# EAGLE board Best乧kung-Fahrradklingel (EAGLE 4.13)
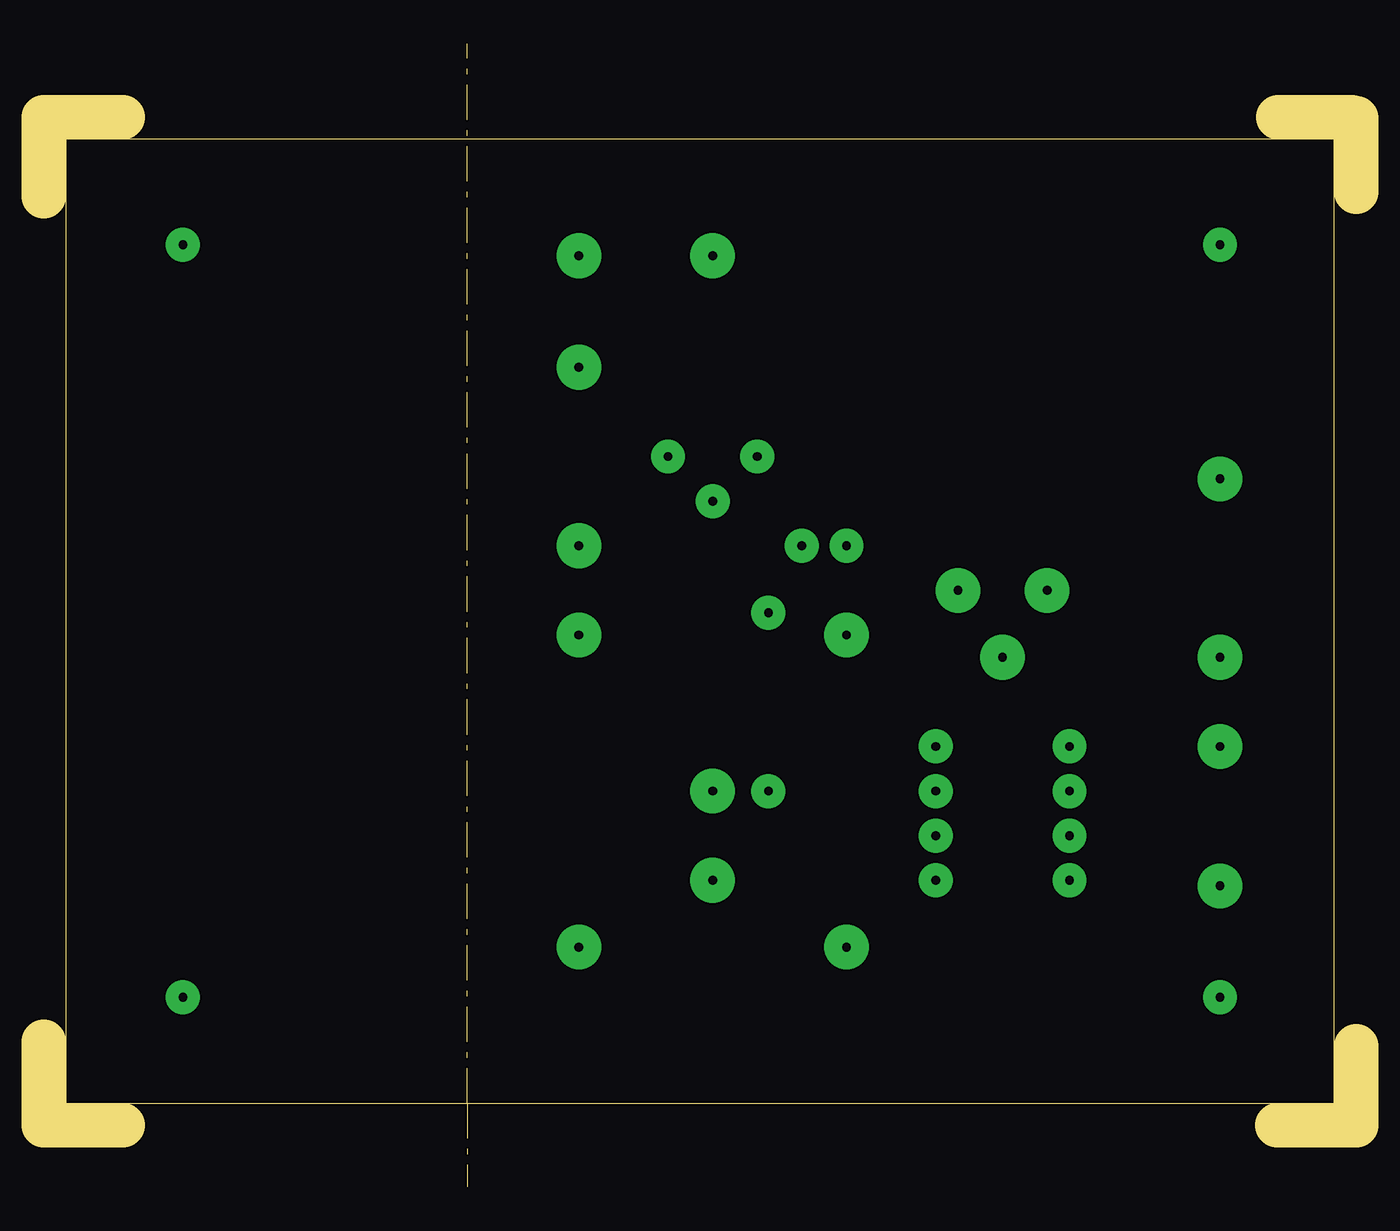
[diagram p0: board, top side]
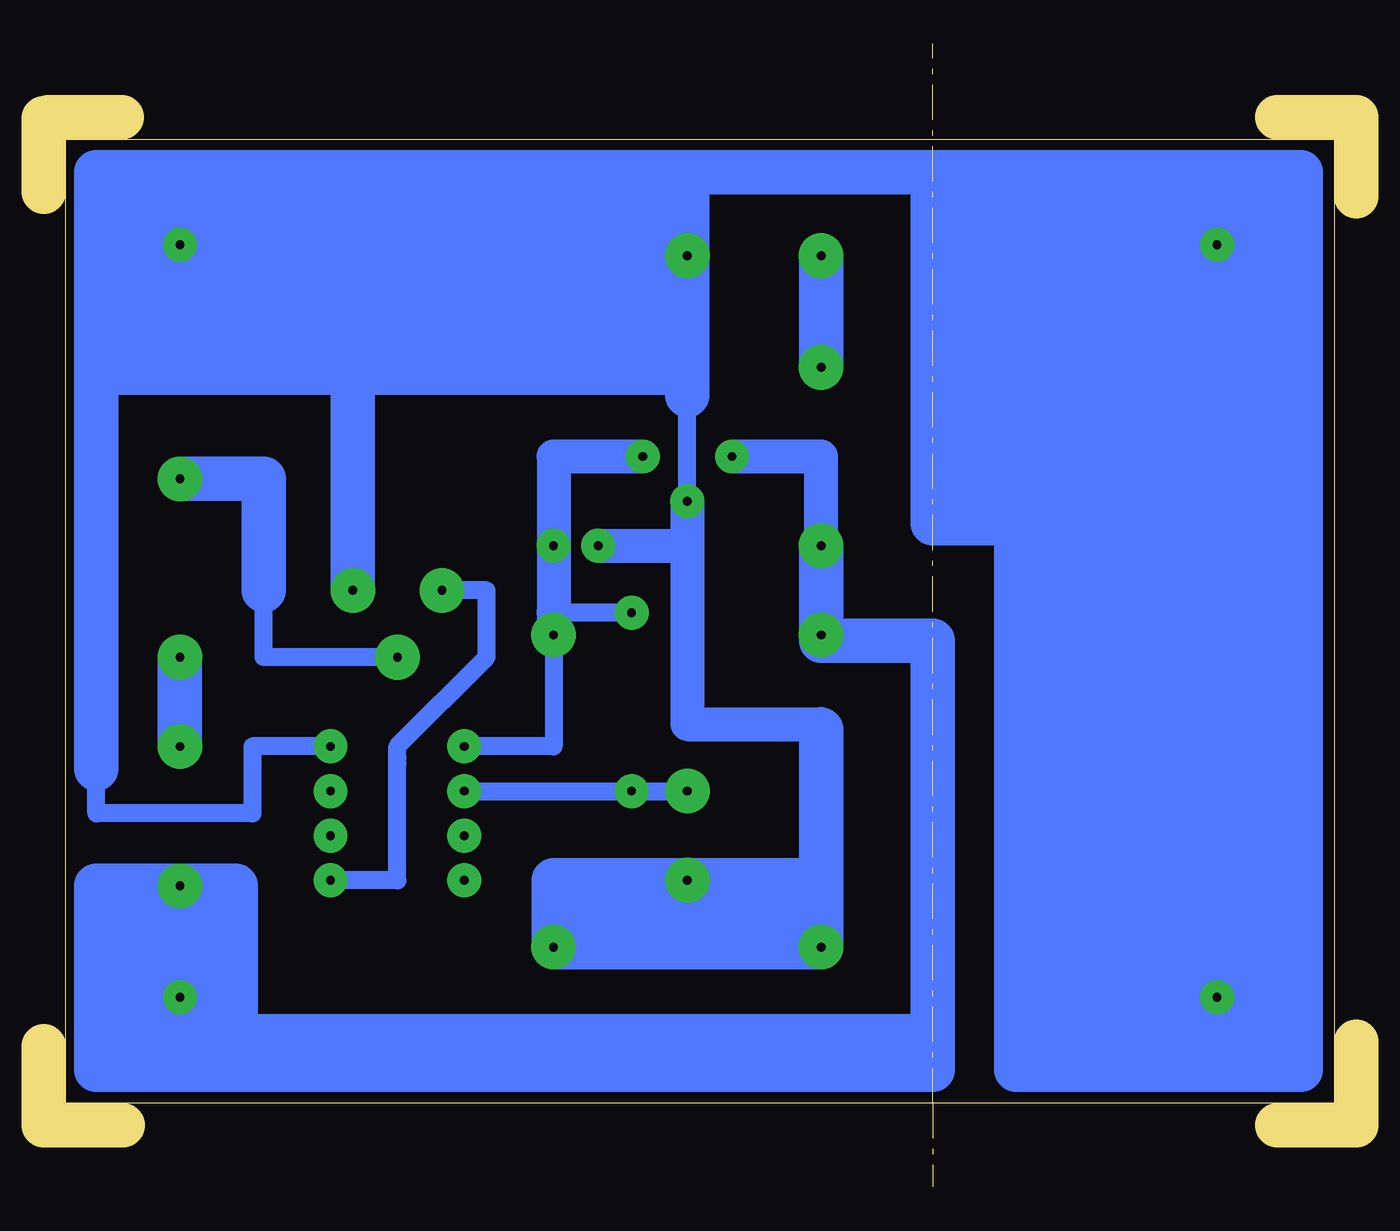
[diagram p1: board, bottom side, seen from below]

Size 74.72 x 65.09 mm. Coordinates in mm from the lower left corner, seen from the top.
Outline: 24.11,4.76 1.25,4.76 1.25,59.67 73.47,59.67 73.47,4.76 24.11,4.76
Outline: 0,56.42 0,60.92 4.5,60.92
Outline: 0,3.76 0,8.26
Outline: 4.5,3.51 0,3.51
Outline: 74.72,60.85 74.72,56.67
Outline: 74.72,8.01 74.72,3.51 70.22,3.51
Outline: 70.29,60.92 74.47,60.92
Outline: 24.11,4.76 24.11,65.09
Outline: 24.11,4.76 24.11,0
Copper layers (1*16): Top 0.035mm / dielectric 1.5mm / Bottom 0.035mm
Design rules "default": minimum track width 10mil, minimum drill 24mil, track to track 8mil, track to pad 8mil, pad to pad 8mil, via to via 8mil, smd to smd 8mil, copper to edge 40mil, drill to drill 8mil, minimum pad ring 10mil, minimum via ring 8mil, stop-mask expansion 4mil, vias tented up to drill 0mil, thermal gap 10mil

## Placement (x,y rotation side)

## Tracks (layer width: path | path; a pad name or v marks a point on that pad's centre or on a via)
S$1  (via drill 0.5 pad 1.93)
  other vias: 7.92,10.79
S$2  (via drill 0.5 pad 1.93)
  other vias: 7.92,53.66
S$3  (via drill 0.5 pad 1.93)
  other vias: 66.97,53.66
S$4  (via drill 0.5 pad 1.93)
  other vias: 66.97,10.79
S$5  (via drill 0.5 pad 2.54)
  Bottom 0.406: v30.46,53.02 v30.46,46.67
  Bottom 2.54: v30.46,53.02 v30.46,46.67
S$6  (via drill 0.5 pad 2.54)
  Bottom 0.406: v66.97,30.16 v66.97,25.08
  Bottom 2.54: v66.97,30.16 v66.97,25.08
S$7
  Bottom 2.54: 71.73,46.04 71.73,23.81
S$8  (via drill 0.5 pad 1.93, 0.5 pad 2.54)
  Bottom 0.406: v30.46,36.51 v30.46,31.43 24.11,31.43 24.11,8.57
  Bottom 1.93: v35.54,41.59 30.46,41.59 v30.46,36.51
  Bottom 2.54: v30.46,31.43 v30.46,36.51 | 30.46,31.11 24.11,31.11 24.11,8.57 | 71.73,14.6 71.73,6.67 24.11,6.67 24.11,8.57 | 71.73,14.6 71.73,16.19 | 24.11,8.57 64.12,8.57 | 71.73,14.6 71.73,17.15 v66.97,17.15 63.8,17.15 63.8,7.3
S$9  (via drill 0.5 pad 1.93, 0.5 pad 2.54)
  Bottom 0.406: 45.7,22.54 46.65,22.54 | 46.65,22.54 v50.78,22.54 | v38.08,22.54 v41.26,22.54 46.65,22.54
  Bottom 1.016: v50.78,22.54 v41.26,22.54 v38.08,22.54
S$11  (via drill 0.5 pad 1.93)
  other vias: 50.78,20
S$12  (via drill 0.5 pad 1.93)
  other vias: 50.78,17.46
S$13  (via drill 0.5 pad 1.93, 0.5 pad 2.54)
  Bottom 1.016: v45.7,31.43 45.7,25.08 v50.78,25.08 | v41.26,32.7 45.7,32.7
  Bottom 1.93: v40.62,41.59 45.7,41.59 v45.7,36.51 45.7,32.7 v45.7,31.43
S$14  (via drill 0.5 pad 1.93)
  other vias: 58.4,22.54
S$15  (via drill 0.5 pad 1.93)
  other vias: 58.4,20
S$16  (via drill 0.5 pad 1.93, 0.5 pad 2.54)
  Bottom 1.016: v58.4,17.46 54.59,17.46 54.59,24.13 | 54.59,24.13 54.59,24.45 | 54.59,24.13 54.59,25.08 49.51,30.16 49.51,33.97 v52.05,33.97
S$18  (via drill 0.5 pad 1.93)
  Bottom 1.016: v58.4,25.08 62.84,25.08 62.84,21.27 71.73,21.27 71.73,24.77
S$19  (via drill 0.5 pad 1.93, 0.5 pad 2.54)
  Bottom 0.406: 38.08,13.65 v45.7,13.65
  Bottom 1.016: v38.08,39.05 38.08,45.08 38.08,46.36 | v38.08,17.46 38.08,13.65 v30.46,13.65 v45.7,13.65
  Bottom 1.93: v38.08,39.05 38.08,36.51 | 38.08,36.51 38.08,26.35 30.46,26.35 30.78,17.46 v30.46,13.65 | v43.16,36.51 38.08,36.51
  Bottom 2.54: 38.08,57.79 v38.08,53.02 38.08,46.67 | 38.08,57.79 3.16,57.79 3.16,6.67 19.35,6.67 19.35,57.47 | 38.08,46.67 38.08,46.36 56.81,46.36 | 56.81,46.36 57.13,46.36 v57.13,33.97 | 38.08,46.67 38.08,45.08 | 30.78,17.46 v38.08,17.46 45.7,17.46 v45.7,13.65 v30.46,13.65 30.46,26.04 | 38.08,57.79 71.73,57.79 71.73,46.36 56.81,46.36
S$20  (via drill 0.5 pad 2.54)
  Bottom 1.016: v54.59,30.16 62.21,30.16 62.21,33.97 | 62.21,40.32 64.43,40.32
  Bottom 2.54: 64.43,40.32 v66.97,40.32 62.21,40.32 62.21,33.97
S$22
  Bottom 2.54: 19.66,37.78 24.11,37.78 24.11,57.47
(copper drawn outside any net)
  shapes: Bottom area x6

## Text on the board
Vias: Auf Bestückungsseite gesehen !
Dimension: IRF1010N | Cevausit 1,5mm dick | alles mit 0,8mm vorgebohrt | Aufbohren wie folgt: | G | S | D
tOrigins: 78L05 | 9V Batterie | und Drucktasten-Schalter | + | Ausg. | Eing. | Masse | µA78L05 | Ausg. | 1N4002 | 1N4002 | IRF1010 | Kat | Eing. | 47n | 10 | S | G | + | + | D | 1 | 10K | 8 | Katode | Anode | Lautsp. | mit Kat | 47µA/16V | 47µA/16V | Schalter | 4 | 5 | gekennzeichnet | hier im Plan | Batterie-Platz | PIC12F629 | Diode 1N4002 1,0mm | Mosfet IRF1010N 1,0mm | 4Stck. Befestigungsbohr... 3,2mm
